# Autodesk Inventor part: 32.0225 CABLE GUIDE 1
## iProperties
Created: 2012-10
Part Number: 32.0225 CABLE GUIDE 1
Document SubType Name: Modeling
Designer: Administrator
Density: 1.4 g/cm^3
Material: PVC-U
Mass: 11.8444 g
Surface Area: 49.1851 cm^2
Volume: 8.46032 cm^3
Author: Administrator
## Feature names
1. Base1
